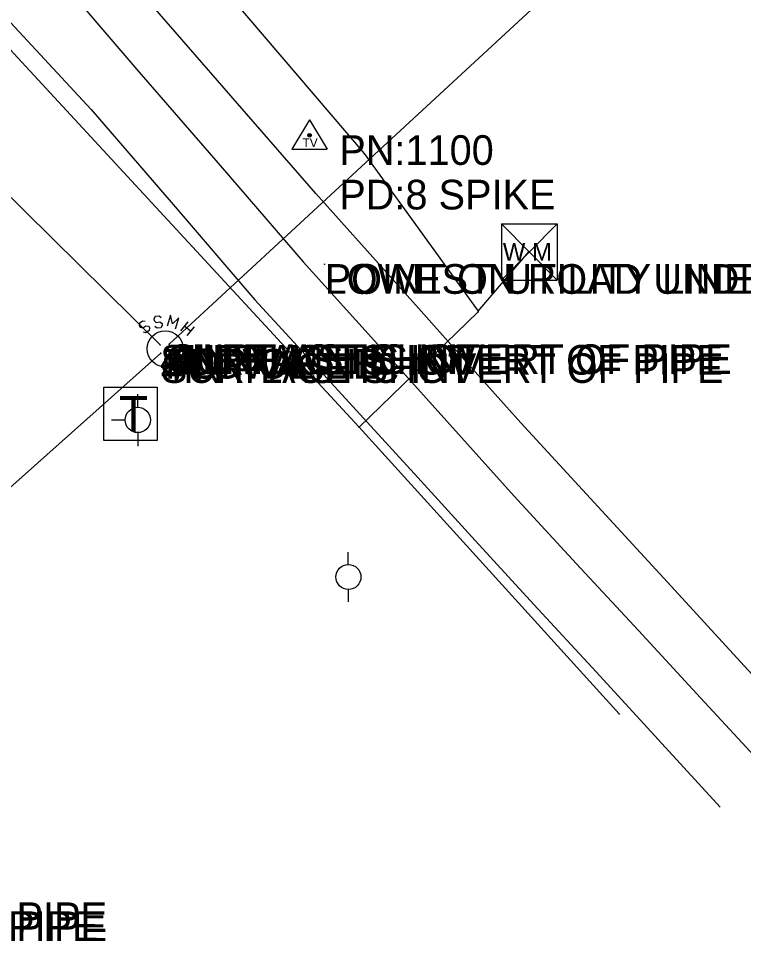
# Model space of a CAD drawing. Extents: x 1660112 to 1662239, y 668919 to 671377.
# Drawn here: x 1661680.1 to 1661802.3, y 669645.1 to 669800.5 of the extents above; entities that cross this region are included whole.
import ezdxf

# ---------------------------------------------------------------- set-up
doc = ezdxf.new("R2010")
doc.units = 0
for name, color, linetype in [('S_EDGE_PAVEMENT', 7, 'Continuous'), ('S_ELECTRIC_UTILITIES_ANNOT', 7, 'Continuous'), ('S_GRD_PT_SYM', 7, 'Continuous'), ('S_MANHOLE_ANNOT', 7, 'Continuous'), ('S_MISC_TOPO_POINT', 7, 'Continuous'), ('S_MSC_PT_SYM', 7, 'Continuous'), ('S_PAVEMENT_CROWN', 7, 'Continuous'), ('S_SANITARY_SEWER', 7, 'Continuous'), ('S_SANITARY_SEWER_ANNOT', 7, 'Continuous'), ('S_SECONDARY_CTL', 7, 'Continuous'), ('S_SECONDARY_CTL_ANNOT', 7, 'Continuous'), ('S_SURVEY_TEXT_ANNOT', 7, 'Continuous'), ('S_TELEPHONE_UTILITIES', 7, 'Continuous'), ('S_UTILITY_POLE', 7, 'Continuous'), ('S_UTL_PT_SYM', 7, 'Continuous'), ('S_WATER_UTILITIES', 7, 'Continuous')]:
    doc.layers.add(name, color=color, linetype=linetype)

msp = doc.modelspace()

# ---------------------------------------------------------------- linework, layer by layer
at = {"layer": 'S_EDGE_PAVEMENT'}
for points in [[(1661814.09, 669678.75), (1661801.76, 669692.17), (1661789.43, 669705.59), (1661777.09, 669719), (1661764.76, 669732.42), (1661756.13, 669742.08), (1661747.5, 669751.75), (1661738.87, 669761.41), (1661730.24, 669771.08), (1661715.94, 669787.51), (1661701.63, 669803.94), (1661687.11, 669820.98), (1661672.59, 669838.02), (1661659.03, 669853.81), (1661645.46, 669869.6), (1661641.26, 669881.81), (1661638.86, 669893.94), (1661637.77, 669899.62)], [(1661587.69, 669853.6), (1661601.46, 669861.14), (1661607.16, 669865.14), (1661611.7, 669864.55), (1661620.99, 669860.83), (1661627.24, 669857.2), (1661632.97, 669852.86), (1661640.64, 669844.85), (1661642.88, 669839.37), (1661651.88, 669829.25), (1661660.88, 669819.13), (1661676.63, 669802.18), (1661692.38, 669785.23), (1661706.18, 669769.2), (1661719.98, 669753.17), (1661729.11, 669743.19), (1661738.25, 669733.2), (1661747.38, 669723.22), (1661756.51, 669713.23), (1661766.96, 669701.85), (1661777.42, 669690.46), (1661787.87, 669679.07), (1661798.32, 669667.68)]]:
    msp.add_lwpolyline(points, dxfattribs=at)
at = {"layer": 'S_GRD_PT_SYM'}
for points in [[(1661704.02, 669745.54), (1661704.02, 669745.59), (1661704.02, 669745.54), (1661703.97, 669745.54), (1661704.02, 669745.54), (1661704.02, 669745.49), (1661704.02, 669745.54), (1661704.07, 669745.54)], [(1661705.52, 669745.65), (1661705.52, 669745.7), (1661705.52, 669745.65), (1661705.47, 669745.65), (1661705.52, 669745.65), (1661705.52, 669745.6), (1661705.52, 669745.65), (1661705.57, 669745.65)], [(1661704.13, 669744.15), (1661704.13, 669744.2), (1661704.13, 669744.15), (1661704.08, 669744.15), (1661704.13, 669744.15), (1661704.13, 669744.1), (1661704.13, 669744.15), (1661704.18, 669744.15)]]:
    msp.add_lwpolyline(points, dxfattribs=at)
at = {"layer": 'S_MSC_PT_SYM'}
msp.add_lwpolyline([(1661731.71, 669759.16), (1661731.71, 669759.21), (1661731.71, 669759.16), (1661731.66, 669759.16), (1661731.71, 669759.16), (1661731.71, 669759.11), (1661731.71, 669759.16), (1661731.76, 669759.16)], dxfattribs=at)
at = {"layer": 'S_PAVEMENT_CROWN'}
msp.add_lwpolyline([(1661620.71, 669884.35), (1661629.13, 669874.34), (1661637.54, 669864.33), (1661653.63, 669845.85), (1661669.73, 669827.36), (1661684.9, 669809.66), (1661700.07, 669791.96), (1661714.09, 669775.77), (1661728.11, 669759.57), (1661736.98, 669749.7), (1661745.86, 669739.83), (1661754.73, 669729.96), (1661763.61, 669720.09), (1661774.08, 669708.76), (1661784.55, 669697.43), (1661795.03, 669686.1), (1661805.5, 669674.77)], dxfattribs=at)
at = {"layer": 'S_SANITARY_SEWER'}
for p, q in [((1661704.02, 669745.54), (1661292.91, 670150.69)), ((1661863.13, 669891.41), (1661705.52, 669745.65)), ((1661700.53, 669749.19), (1661700.46, 669748.8)), ((1661701.08, 669749.58), (1661700.53, 669749.19)), ((1661701.5, 669749.5), (1661701.08, 669749.58)), ((1661707.51, 669747.95), (1661708.75, 669749.42)), ((1661700.46, 669748.8), (1661700.65, 669748.53)), ((1661700.65, 669748.53), (1661701.08, 669748.41)), ((1661701.08, 669748.41), (1661701.62, 669748.76)), ((1661701.62, 669747.6), (1661701.23, 669747.68)), ((1661701.62, 669748.76), (1661702.08, 669748.69)), ((1661702.16, 669747.99), (1661701.62, 669747.6)), ((1661702.08, 669748.69), (1661702.24, 669748.41)), ((1661702.24, 669748.41), (1661702.16, 669747.99)), ((1661708.17, 669748.72), (1661709.14, 669747.91)), ((1661709.72, 669748.61), (1661708.48, 669747.14)), ((1661704.13, 669744.15), (1661600.32, 669651.65))]:
    msp.add_line(p, q, dxfattribs=at)
for points in [[(1661704.18, 669750.12), (1661703.83, 669750.39), (1661703.17, 669750.31), (1661702.94, 669749.96), (1661702.98, 669749.65), (1661703.32, 669749.34), (1661703.94, 669749.46), (1661704.33, 669749.15), (1661704.37, 669748.84), (1661704.1, 669748.45), (1661703.48, 669748.38), (1661703.13, 669748.65)], [(1661706.62, 669748.26), (1661707.16, 669750.12), (1661706.11, 669749.11), (1661705.73, 669750.55), (1661705.18, 669748.69)]]:
    msp.add_lwpolyline(points, dxfattribs=at)
msp.add_circle((1661704.86, 669744.89), 3.05, dxfattribs=at)
at = {"layer": 'S_SECONDARY_CTL'}
for p, q in [((1661729.17, 669783.48), (1661726.16, 669778.53)), ((1661729.17, 669783.48), (1661732.12, 669778.53)), ((1661726.16, 669778.53), (1661732.12, 669778.53))]:
    msp.add_line(p, q, dxfattribs=at)
for radius in [0.311, 0.183, 0.103]:
    msp.add_circle((1661729.17, 669780.87), radius, dxfattribs=at)
at = {"layer": 'S_TELEPHONE_UTILITIES'}
msp.add_lwpolyline([(1661694.52, 669729.44), (1661694.52, 669738.44), (1661703.52, 669738.44), (1661703.52, 669729.44)], close=True, dxfattribs=at)
at = {"layer": 'S_UTILITY_POLE'}
for p, q in [((1661700.23, 669735.02), (1661700.23, 669737.26)), ((1661698.14, 669732.89), (1661695.82, 669732.89)), ((1661700.31, 669728.47), (1661700.31, 669730.79)), ((1661735.69, 669708.55), (1661735.69, 669710.67)), ((1661735.69, 669704.33), (1661735.69, 669702.27))]:
    msp.add_line(p, q, dxfattribs=at)
for centre, radius in [((1661700.24, 669732.91), 2.13), ((1661735.71, 669706.47), 2.11)]:
    msp.add_circle(centre, radius, dxfattribs=at)
at = {"layer": 'S_UTL_PT_SYM'}
for points in [[(1661738.35, 669777.77), (1661738.35, 669777.82), (1661738.35, 669777.77), (1661738.3, 669777.77), (1661738.35, 669777.77), (1661738.35, 669777.72), (1661738.35, 669777.77), (1661738.4, 669777.77)], [(1661766.11, 669761.24), (1661766.11, 669761.29), (1661766.11, 669761.24), (1661766.06, 669761.24), (1661766.11, 669761.24), (1661766.11, 669761.19), (1661766.11, 669761.24), (1661766.16, 669761.24)], [(1661731.71, 669759.16), (1661731.71, 669759.21), (1661731.71, 669759.16), (1661731.66, 669759.16), (1661731.71, 669759.16), (1661731.71, 669759.11), (1661731.71, 669759.16), (1661731.76, 669759.16)], [(1661757.57, 669751.13), (1661757.57, 669751.18), (1661757.57, 669751.13), (1661757.52, 669751.13), (1661757.57, 669751.13), (1661757.57, 669751.08), (1661757.57, 669751.13), (1661757.62, 669751.13)], [(1661757.59, 669751.24), (1661757.59, 669751.29), (1661757.59, 669751.24), (1661757.54, 669751.24), (1661757.59, 669751.24), (1661757.59, 669751.19), (1661757.59, 669751.24), (1661757.64, 669751.24)], [(1661704.02, 669745.54), (1661704.02, 669745.59), (1661704.02, 669745.54), (1661703.97, 669745.54), (1661704.02, 669745.54), (1661704.02, 669745.49), (1661704.02, 669745.54), (1661704.07, 669745.54)], [(1661704.86, 669744.89), (1661704.86, 669744.94), (1661704.86, 669744.89), (1661704.81, 669744.89), (1661704.86, 669744.89), (1661704.86, 669744.84), (1661704.86, 669744.89), (1661704.91, 669744.89)], [(1661705.52, 669745.65), (1661705.52, 669745.7), (1661705.52, 669745.65), (1661705.47, 669745.65), (1661705.52, 669745.65), (1661705.52, 669745.6), (1661705.52, 669745.65), (1661705.57, 669745.65)], [(1661704.13, 669744.15), (1661704.13, 669744.2), (1661704.13, 669744.15), (1661704.08, 669744.15), (1661704.13, 669744.15), (1661704.13, 669744.1), (1661704.13, 669744.15), (1661704.18, 669744.15)], [(1661737.48, 669731.75), (1661737.48, 669731.8), (1661737.48, 669731.75), (1661737.43, 669731.75), (1661737.48, 669731.75), (1661737.48, 669731.7), (1661737.48, 669731.75), (1661737.53, 669731.75)], [(1661737.54, 669731.67), (1661737.54, 669731.72), (1661737.54, 669731.67), (1661737.49, 669731.67), (1661737.54, 669731.67), (1661737.54, 669731.62), (1661737.54, 669731.67), (1661737.59, 669731.67)], [(1661781.33, 669683.42), (1661781.33, 669683.47), (1661781.33, 669683.42), (1661781.28, 669683.42), (1661781.33, 669683.42), (1661781.33, 669683.37), (1661781.33, 669683.42), (1661781.38, 669683.42)]]:
    msp.add_lwpolyline(points, dxfattribs=at)
at = {"layer": 'S_WATER_UTILITIES'}
for p, q in [((1661706.34, 669815.34), (1661738.35, 669777.77)), ((1661737.48, 669731.75), (1661674.04, 669800.4)), ((1661738.35, 669777.77), (1661757.59, 669751.24)), ((1661761.52, 669765.96), (1661770.86, 669765.96)), ((1661761.52, 669765.96), (1661761.52, 669756.47)), ((1661761.52, 669765.96), (1661770.86, 669756.47)), ((1661770.86, 669765.96), (1661761.52, 669756.47)), ((1661770.86, 669765.96), (1661770.86, 669756.47)), ((1661757.59, 669751.24), (1661766.11, 669761.24)), ((1661761.52, 669756.47), (1661770.86, 669756.47)), ((1661757.57, 669751.13), (1661737.54, 669731.67)), ((1661737.54, 669731.67), (1661781.33, 669683.42))]:
    msp.add_line(p, q, dxfattribs=at)

# ---------------------------------------------------------------- texts
at = {"layer": 'S_ELECTRIC_UTILITIES_ANNOT'}
msp.add_text('LOWEST UTILITY LINE', height=5, dxfattribs=at).set_placement((1661731.71, 669754.16))
at = {"layer": 'S_MANHOLE_ANNOT'}
msp.add_text('FLOW LINE', height=5, dxfattribs=at).set_placement((1661704.86, 669739.89))
at = {"layer": 'S_MISC_TOPO_POINT'}
for p in [(1661704.02, 669740.54), (1661705.52, 669740.65), (1661704.13, 669739.15)]:
    msp.add_text('SURFACE SHOT', height=5, dxfattribs=at).set_placement(p)
at = {"layer": 'S_SANITARY_SEWER_ANNOT'}
for s, p in [('4IN PLASTIC INVERT OF PIPE', (1661704.02, 669740.54)), ('TOP OF LID', (1661704.86, 669739.89)), ('4IN PLASTIC INVERT OF PIPE', (1661705.52, 669740.65)), ('4IN PLASTIC INVERT OF PIPE', (1661704.13, 669739.15)), ('4IN PLASTIC INVERT OF PIPE', (1661600.32, 669646.65)), ('4IN PLASTIC INVERT OF PIPE', (1661598.89, 669645.17)), ('4IN PLASTIC INVERT OF PIPE', (1661600.3, 669645.13))]:
    msp.add_text(s, height=5, dxfattribs=at).set_placement(p)
at = {"layer": 'S_SECONDARY_CTL'}
msp.add_text('TV', height=1.5, rotation=360, dxfattribs=at).set_placement((1661727.97, 669778.86))
at = {"layer": 'S_SECONDARY_CTL_ANNOT'}
for s, p in [('PN:1100', (1661734.17, 669775.87)), ('PD:8 SPIKE', (1661734.17, 669768.37))]:
    msp.add_text(s, height=5, dxfattribs=at).set_placement(p)
at = {"layer": 'S_SURVEY_TEXT_ANNOT'}
msp.add_text('POINT ON ROAD UNDER LOWES', height=5, dxfattribs=at).set_placement((1661731.71, 669754.16))
at = {"layer": 'S_TELEPHONE_UTILITIES'}
msp.add_text('T', height=6, rotation=360, dxfattribs=at).set_placement((1661697.09, 669730.94))
at = {"layer": 'S_WATER_UTILITIES'}
msp.add_text('W M', height=3, rotation=360, dxfattribs=at).set_placement((1661761.72, 669759.73))

doc.saveas('drawing.dxf')
